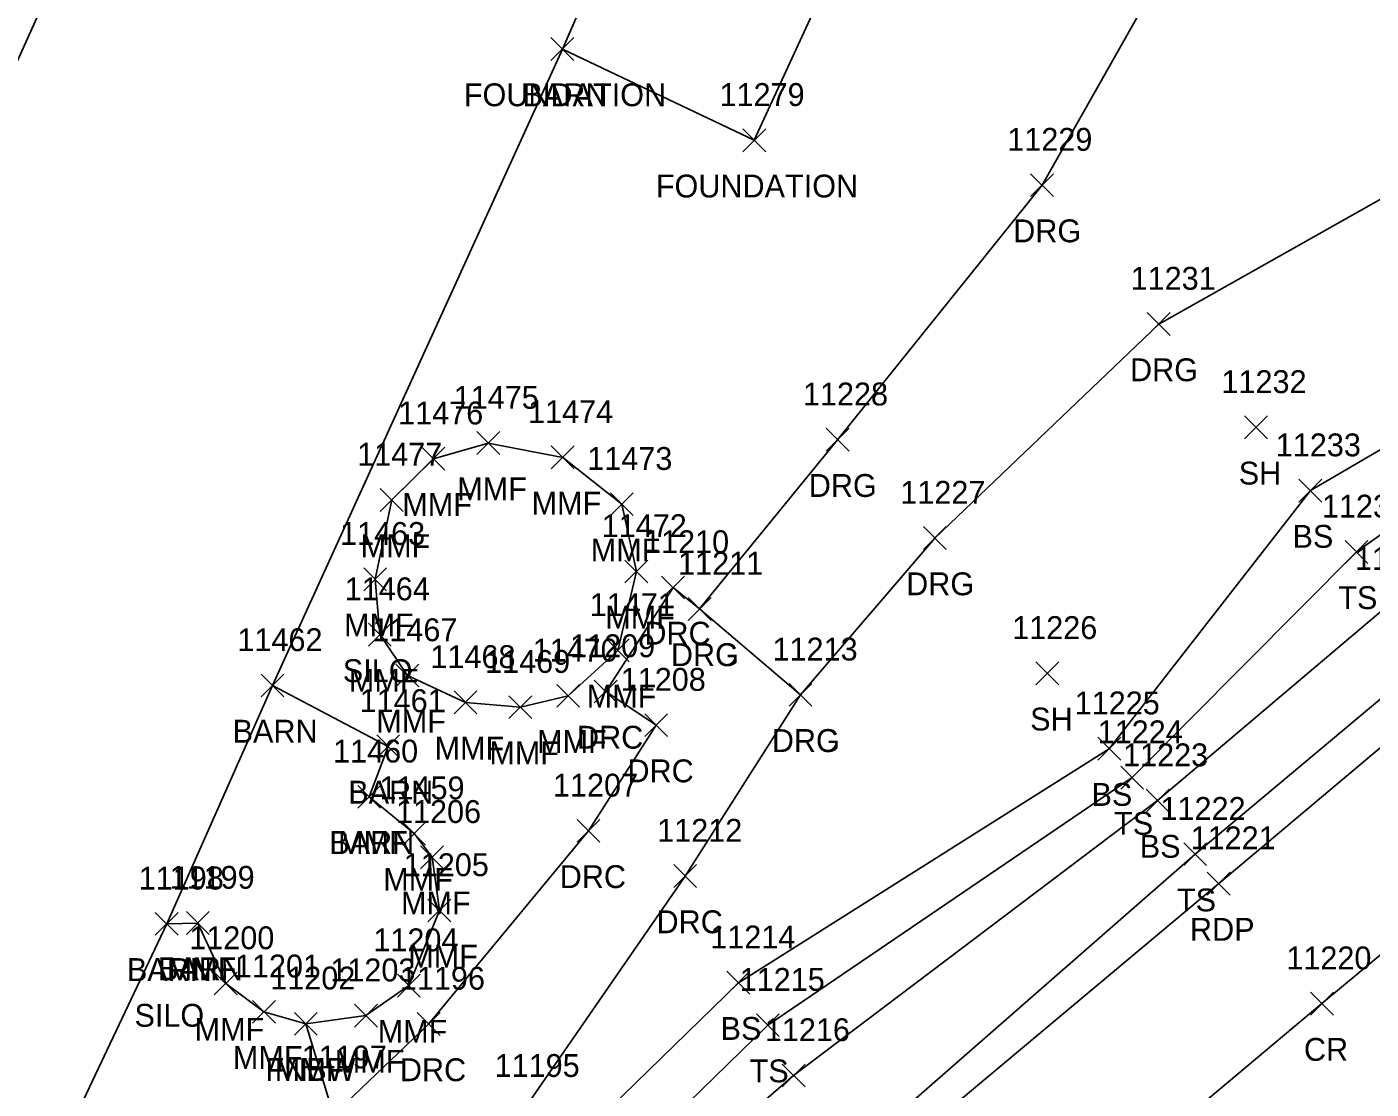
# Model space of a CAD drawing. Extents: x 1475671 to 1477951, y 592661 to 593821.
# Drawn here: x 1476740.9 to 1476858.4, y 593332 to 593424.9 of the extents above; entities that cross this region are included whole.
import ezdxf

# ---------------------------------------------------------------- set-up
doc = ezdxf.new("R2010")
doc.units = 0
for name, color, linetype in [('L_A', 7, 'Continuous'), ('L_C', 7, 'Continuous'), ('L_I', 7, 'Continuous'), ('L_TIC', 7, 'Continuous'), ('LBC', 7, 'Continuous'), ('LDEFAULT', 7, 'Continuous'), ('LELB', 7, 'Continuous'), ('LFNC', 7, 'Continuous'), ('P_A', 7, 'Continuous'), ('P_I', 7, 'Continuous'), ('P_TIC', 7, 'Continuous'), ('PET', 7, 'Continuous'), ('PRC', 7, 'Continuous'), ('R_A', 7, 'Continuous'), ('R_I', 7, 'Continuous'), ('R_TIC', 7, 'Continuous'), ('RDG', 7, 'Continuous'), ('RDP', 7, 'Continuous')]:
    doc.layers.add(name, color=color, linetype=linetype)

msp = doc.modelspace()

# ---------------------------------------------------------------- linework, layer by layer
at = {"layer": 'L_TIC'}
for points in [[(1476786.68, 593422.01), (1476788.68, 593424.01)], [(1476788.68, 593422.01), (1476786.68, 593424.01)], [(1476786.68, 593422.01), (1476788.68, 593424.01)], [(1476788.68, 593422.01), (1476786.68, 593424.01)], [(1476803.46, 593414.03), (1476805.46, 593416.03)], [(1476805.46, 593414.03), (1476803.46, 593416.03)], [(1476847.31, 593388.92), (1476849.31, 593390.92)], [(1476849.31, 593388.92), (1476847.31, 593390.92)], [(1476780.21, 593387.55), (1476782.21, 593389.55)], [(1476782.21, 593387.55), (1476780.21, 593389.55)], [(1476775.41, 593386.18), (1476777.41, 593388.18)], [(1476777.41, 593386.18), (1476775.41, 593388.18)], [(1476786.71, 593386.3), (1476788.71, 593388.3)], [(1476788.71, 593386.3), (1476786.71, 593388.3)], [(1476771.77, 593382.57), (1476773.77, 593384.57)], [(1476773.77, 593382.57), (1476771.77, 593384.57)], [(1476771.77, 593382.57), (1476773.77, 593384.57)], [(1476773.77, 593382.57), (1476771.77, 593384.57)], [(1476852.06, 593383.39), (1476854.06, 593385.39)], [(1476854.06, 593383.39), (1476852.06, 593385.39)], [(1476791.88, 593382.2), (1476793.88, 593384.2)], [(1476793.88, 593382.2), (1476791.88, 593384.2)], [(1476856.09, 593378.03), (1476858.09, 593380.03)], [(1476858.09, 593378.03), (1476856.09, 593380.03)], [(1476770.32, 593375.64), (1476772.32, 593377.64)], [(1476772.32, 593375.64), (1476770.32, 593377.64)], [(1476770.32, 593375.64), (1476772.32, 593377.64)], [(1476772.32, 593375.64), (1476770.32, 593377.64)], [(1476793.15, 593376.32), (1476795.15, 593378.32)], [(1476795.15, 593376.32), (1476793.15, 593378.32)], [(1476770.73, 593370.8), (1476772.73, 593372.8)], [(1476772.73, 593370.8), (1476770.73, 593372.8)], [(1476791.53, 593369.42), (1476793.53, 593371.42)], [(1476793.53, 593369.42), (1476791.53, 593371.42)], [(1476829.08, 593367.41), (1476831.08, 593369.41)], [(1476831.08, 593367.41), (1476829.08, 593369.41)], [(1476761.35, 593366.35), (1476763.35, 593368.35)], [(1476763.35, 593366.35), (1476761.35, 593368.35)], [(1476761.35, 593366.35), (1476763.35, 593368.35)], [(1476763.35, 593366.35), (1476761.35, 593368.35)], [(1476773.14, 593367.22), (1476775.14, 593369.22)], [(1476775.14, 593367.22), (1476773.14, 593369.22)], [(1476787.19, 593365.44), (1476789.19, 593367.44)], [(1476789.19, 593365.44), (1476787.19, 593367.44)], [(1476778.22, 593364.87), (1476780.22, 593366.87)], [(1476780.22, 593364.87), (1476778.22, 593366.87)], [(1476783.01, 593364.45), (1476785.01, 593366.45)], [(1476785.01, 593364.45), (1476783.01, 593366.45)], [(1476771.46, 593361.02), (1476773.46, 593363.02)], [(1476773.46, 593361.02), (1476771.46, 593363.02)], [(1476834.49, 593360.82), (1476836.49, 593362.82)], [(1476836.49, 593360.82), (1476834.49, 593362.82)], [(1476836.49, 593358.29), (1476838.49, 593360.29)], [(1476838.49, 593358.29), (1476836.49, 593360.29)], [(1476769.8, 593356.61), (1476771.8, 593358.61)], [(1476771.8, 593356.61), (1476769.8, 593358.61)], [(1476769.8, 593356.61), (1476771.8, 593358.61)], [(1476771.8, 593356.61), (1476769.8, 593358.61)], [(1476838.71, 593356.28), (1476840.71, 593358.28)], [(1476840.71, 593356.28), (1476838.71, 593358.28)], [(1476773.73, 593353.39), (1476775.73, 593355.39)], [(1476775.73, 593353.39), (1476773.73, 593355.39)], [(1476775.29, 593351.32), (1476777.29, 593353.32)], [(1476777.29, 593351.32), (1476775.29, 593353.32)], [(1476841.99, 593351.59), (1476843.99, 593353.59)], [(1476843.99, 593351.59), (1476841.99, 593353.59)], [(1476775.93, 593346.67), (1476777.93, 593348.67)], [(1476777.93, 593346.67), (1476775.93, 593348.67)], [(1476752.1, 593345.5), (1476754.1, 593347.5)], [(1476754.1, 593345.5), (1476752.1, 593347.5)], [(1476752.1, 593345.5), (1476754.1, 593347.5)], [(1476754.1, 593345.5), (1476752.1, 593347.5)], [(1476754.82, 593345.57), (1476756.82, 593347.57)], [(1476756.82, 593345.57), (1476754.82, 593347.57)], [(1476754.82, 593345.57), (1476756.82, 593347.57)], [(1476756.82, 593345.57), (1476754.82, 593347.57)], [(1476757.26, 593340.28), (1476759.26, 593342.28)], [(1476759.26, 593340.28), (1476757.26, 593342.28)], [(1476802.07, 593340.35), (1476804.07, 593342.35)], [(1476804.07, 593340.35), (1476802.07, 593342.35)], [(1476773.26, 593340.1), (1476775.26, 593342.1)], [(1476775.26, 593340.1), (1476773.26, 593342.1)], [(1476760.6, 593337.81), (1476762.6, 593339.81)], [(1476762.6, 593337.81), (1476760.6, 593339.81)], [(1476764.26, 593336.76), (1476766.26, 593338.76)], [(1476766.26, 593336.76), (1476764.26, 593338.76)], [(1476764.26, 593336.76), (1476766.26, 593338.76)], [(1476766.26, 593336.76), (1476764.26, 593338.76)], [(1476769.51, 593337.47), (1476771.51, 593339.47)], [(1476771.51, 593337.47), (1476769.51, 593339.47)], [(1476804.64, 593336.64), (1476806.64, 593338.64)], [(1476806.64, 593336.64), (1476804.64, 593338.64)], [(1476806.89, 593332.24), (1476808.89, 593334.24)], [(1476808.89, 593332.24), (1476806.89, 593334.24)]]:
    msp.add_lwpolyline(points, dxfattribs=at)
at = {"layer": 'LBC'}
for points in [[(1476766.99, 593478.72), (1476749.47, 593442.92), (1476737.05, 593415.38), (1476717.88, 593373.12), (1476703.46, 593340.35), (1476741.92, 593322.87), (1476753.1, 593346.5), (1476762.35, 593367.35), (1476787.68, 593423.01), (1476791.87, 593432.58)], [(1476803.32, 593462.28), (1476822.31, 593453.8), (1476804.46, 593415.03), (1476787.68, 593423.01)], [(1476770.8, 593357.61), (1476772.46, 593362.02), (1476762.35, 593367.35)], [(1476753.1, 593346.5), (1476755.82, 593346.57)]]:
    msp.add_lwpolyline(points, dxfattribs=at)
at = {"layer": 'LDEFAULT'}
for points in [[(1476771.32, 593376.64), (1476771.73, 593371.8), (1476774.14, 593368.22), (1476779.22, 593365.87), (1476784.01, 593365.45), (1476788.19, 593366.44), (1476792.53, 593370.42), (1476794.15, 593377.32), (1476792.88, 593383.2), (1476787.71, 593387.3), (1476781.21, 593388.55), (1476776.41, 593387.18), (1476772.77, 593383.57)], [(1476771.32, 593376.64), (1476772.77, 593383.57)], [(1476755.82, 593346.57), (1476758.26, 593341.28), (1476761.6, 593338.81), (1476765.26, 593337.76), (1476770.51, 593338.47), (1476774.26, 593341.1), (1476776.93, 593347.67), (1476776.29, 593352.32), (1476774.73, 593354.39), (1476770.8, 593357.61)]]:
    msp.add_lwpolyline(points, dxfattribs=at)
at = {"layer": 'LELB'}
for points in [[(1476660.79, 593199.46), (1476674.63, 593214.33), (1476703.92, 593243.37), (1476720.54, 593255.98), (1476751.7, 593282.61), (1476781.77, 593307.79), (1476789.04, 593316.89), (1476807.89, 593333.24), (1476839.71, 593357.28), (1476859.97, 593374.46), (1476882.16, 593391.96), (1476882.87, 593395.08), (1476884.75, 593398.78), (1476886.94, 593401.06), (1476880.92, 593405.09), (1476872.21, 593402.61), (1476869.35, 593406.91), (1476883.46, 593416.6), (1476894.87, 593423.54), (1476922.16, 593439.01), (1476941.74, 593451.3), (1476958.3, 593465.19), (1476973.77, 593478.9)], [(1476525.71, 593116.6), (1476535.99, 593117.47), (1476564.39, 593135.96), (1476604.97, 593161.16), (1476624.83, 593173.86), (1476638.09, 593183.34), (1476660.79, 593199.46), (1476676.81, 593212.32), (1476707.13, 593238.69), (1476723.81, 593252.6), (1476754.14, 593278.44), (1476785.31, 593303.01), (1476812.8, 593326.19), (1476842.99, 593352.59), (1476863.07, 593369.43), (1476886.56, 593389.77), (1476893.66, 593396.85), (1476901.2, 593401.68), (1476921.17, 593422.2)], [(1476709.5, 593251.9), (1476704.63, 593270.28), (1476699.34, 593285.3), (1476723.21, 593287.69), (1476755.77, 593298.72), (1476777.04, 593314.27), (1476785.1, 593323.82), (1476803.07, 593341.35), (1476835.49, 593361.82), (1476853.06, 593384.39), (1476874.85, 593397.11), (1476884.75, 593398.78)], [(1476716.55, 593257.09), (1476712.45, 593265.92), (1476725.15, 593279.89), (1476757.78, 593295.95), (1476779.66, 593309.61), (1476787.04, 593319.52), (1476805.64, 593337.64), (1476837.49, 593359.29), (1476857.09, 593379.03), (1476877.34, 593393.41), (1476882.87, 593395.08)]]:
    msp.add_lwpolyline(points, dxfattribs=at)
at = {"layer": 'LFNC'}
msp.add_lwpolyline([(1476767.35, 593330.85), (1476765.26, 593337.76)], dxfattribs=at)
at = {"layer": 'P_TIC'}
for points in [[(1476844.05, 593349.02), (1476846.05, 593351.02)], [(1476846.05, 593349.02), (1476844.05, 593351.02)], [(1476853.07, 593338.52), (1476855.07, 593340.52)], [(1476855.07, 593338.52), (1476853.07, 593340.52)]]:
    msp.add_lwpolyline(points, dxfattribs=at)
at = {"layer": 'PET'}
msp.add_lwpolyline([(1476459.25, 593078.48), (1476508.39, 593100.17), (1476518.15, 593105.13), (1476565.38, 593131.07), (1476607.43, 593157.45), (1476640.25, 593180.54), (1476678.21, 593210.57), (1476708.64, 593235.75), (1476725.67, 593249.83), (1476755.84, 593275.3), (1476786.3, 593300.73), (1476814.32, 593324.28), (1476845.05, 593350.02), (1476865.02, 593366.82), (1476897.04, 593395.14), (1476922.98, 593419.08), (1476952.36, 593443.37)], dxfattribs=at)
at = {"layer": 'PRC'}
msp.add_lwpolyline([(1476461.98, 593064.62), (1476520.7, 593090.52), (1476540.79, 593101.34), (1476577.67, 593121.61), (1476614.51, 593145.69), (1476649.36, 593170.81), (1476687.02, 593200.01), (1476716.69, 593224.25), (1476733.58, 593238.31), (1476760.9, 593261.21), (1476795.35, 593290.14), (1476823.06, 593313.51), (1476854.07, 593339.52), (1476875.7, 593357.51), (1476907.01, 593384.08), (1476934.06, 593407.68), (1476963.46, 593432.81)], dxfattribs=at)
at = {"layer": 'R_TIC'}
for points in [[(1476828.61, 593410.11), (1476830.61, 593412.11)], [(1476830.61, 593410.11), (1476828.61, 593412.11)], [(1476838.81, 593397.96), (1476840.81, 593399.96)], [(1476840.81, 593397.96), (1476838.81, 593399.96)], [(1476810.74, 593387.84), (1476812.74, 593389.84)], [(1476812.74, 593387.84), (1476810.74, 593389.84)], [(1476819.24, 593379.24), (1476821.24, 593381.24)], [(1476821.24, 593379.24), (1476819.24, 593381.24)], [(1476796.36, 593374.92), (1476798.36, 593376.92)], [(1476798.36, 593374.92), (1476796.36, 593376.92)], [(1476798.68, 593373.04), (1476800.68, 593375.04)], [(1476800.68, 593373.04), (1476798.68, 593375.04)], [(1476798.68, 593373.04), (1476800.68, 593375.04)], [(1476800.68, 593373.04), (1476798.68, 593375.04)], [(1476790.47, 593365.82), (1476792.47, 593367.82)], [(1476792.47, 593365.82), (1476790.47, 593367.82)], [(1476807.5, 593365.53), (1476809.5, 593367.53)], [(1476809.5, 593365.53), (1476807.5, 593367.53)], [(1476807.5, 593365.53), (1476809.5, 593367.53)], [(1476809.5, 593365.53), (1476807.5, 593367.53)], [(1476807.5, 593365.53), (1476809.5, 593367.53)], [(1476809.5, 593365.53), (1476807.5, 593367.53)], [(1476794.88, 593362.88), (1476796.88, 593364.88)], [(1476796.88, 593362.88), (1476794.88, 593364.88)], [(1476788.97, 593353.63), (1476790.97, 593355.63)], [(1476790.97, 593353.63), (1476788.97, 593355.63)], [(1476797.42, 593349.68), (1476799.42, 593351.68)], [(1476799.42, 593349.68), (1476797.42, 593351.68)], [(1476774.99, 593336.74), (1476776.99, 593338.74)], [(1476776.99, 593336.74), (1476774.99, 593338.74)]]:
    msp.add_lwpolyline(points, dxfattribs=at)
at = {"layer": 'RDG'}
for points in [[(1476799.68, 593374.04), (1476811.74, 593388.84), (1476829.61, 593411.11), (1476841.26, 593431.75), (1476824.79, 593454.41)], [(1476808.5, 593366.53), (1476820.24, 593380.24), (1476839.81, 593398.96), (1476864.37, 593412.81), (1476894.87, 593423.54), (1476911.77, 593427.3), (1476921.17, 593422.2), (1476922.98, 593419.08)]]:
    msp.add_lwpolyline(points, dxfattribs=at)
at = {"layer": 'RDP'}
for points in [[(1476741.92, 593322.87), (1476748.15, 593317.64), (1476764.24, 593326.49), (1476775.99, 593337.74), (1476789.97, 593354.63), (1476795.88, 593363.88), (1476791.47, 593366.82), (1476797.36, 593375.92), (1476799.68, 593374.04), (1476808.5, 593366.53)], [(1476703.46, 593340.35), (1476696.1, 593322.41), (1476695.07, 593307.68), (1476704.77, 593300.24), (1476724.04, 593301.34), (1476733.81, 593300.45), (1476747.14, 593305.07), (1476767.96, 593315.71), (1476784.22, 593330.11), (1476798.42, 593350.68), (1476808.5, 593366.53)]]:
    msp.add_lwpolyline(points, dxfattribs=at)

# ---------------------------------------------------------------- texts
at = {"layer": 'L_A'}
for s, p in [('FOUNDATION', (1476779.07, 593418.01)), ('BARN', (1476784.19, 593418.01)), ('FOUNDATION', (1476795.85, 593410.03)), ('SH', (1476846.8, 593384.92)), ('MMF', (1476778.49, 593383.55)), ('MMF', (1476773.69, 593382.18)), ('MMF', (1476784.99, 593382.3)), ('BS', (1476851.5, 593379.39)), ('MMF', (1476770.05, 593378.57)), ('MMF', (1476770.05, 593378.57)), ('MMF', (1476790.16, 593378.2)), ('TS', (1476855.5, 593374.03)), ('MMF', (1476791.43, 593372.32)), ('MMF', (1476768.6, 593371.64)), ('MMF', (1476768.6, 593371.64)), ('MMF', (1476769.02, 593366.8)), ('MMF', (1476789.81, 593365.42)), ('MMF', (1476771.42, 593363.22)), ('SH', (1476828.57, 593363.41)), ('BARN', (1476758.86, 593362.35)), ('BARN', (1476758.86, 593362.35)), ('MMF', (1476785.47, 593361.44)), ('MMF', (1476776.51, 593360.87)), ('MMF', (1476781.3, 593360.45)), ('BARN', (1476768.97, 593357.02)), ('BS', (1476833.93, 593356.82)), ('TS', (1476835.9, 593354.29)), ('BARN', (1476767.31, 593352.61)), ('MMF', (1476768.08, 593352.61)), ('BS', (1476838.15, 593352.28)), ('MMF', (1476772.02, 593349.39)), ('MMF', (1476773.58, 593347.32)), ('TS', (1476841.4, 593347.59)), ('MMF', (1476774.21, 593342.67)), ('BARN', (1476749.62, 593341.5)), ('BARN', (1476749.62, 593341.5)), ('BARN', (1476752.33, 593341.57)), ('MMF', (1476753.1, 593341.57)), ('MMF', (1476755.54, 593336.28)), ('MMF', (1476771.54, 593336.1)), ('BS', (1476801.51, 593336.35)), ('MMF', (1476758.88, 593333.81)), ('MMF', (1476767.79, 593333.47)), ('FNBW', (1476761.73, 593332.76)), ('MMF', (1476762.54, 593332.76)), ('TS', (1476804.05, 593332.64))]:
    msp.add_text(s, height=2, dxfattribs=at).set_placement(p)
at = {"layer": 'L_C'}
for p in [(1476768.49, 593367.64), (1476768.49, 593367.64), (1476750.28, 593337.5), (1476750.28, 593337.5)]:
    msp.add_text('SILO', height=2, dxfattribs=at).set_placement(p)
at = {"layer": 'L_I'}
for s, p in [('11279', (1476801.42, 593418.03)), ('11232', (1476845.29, 593392.92)), ('11475', (1476778.18, 593391.55)), ('11476', (1476773.33, 593390.18)), ('11474', (1476784.68, 593390.3)), ('11233', (1476850.04, 593387.39)), ('11477', (1476769.75, 593386.57)), ('11477', (1476769.75, 593386.57)), ('11473', (1476789.86, 593386.2)), ('11234', (1476854.07, 593382.03)), ('11472', (1476791.12, 593380.32)), ('11463', (1476768.25, 593379.64)), ('11463', (1476768.25, 593379.64)), ('11235', (1476856.95, 593377.46)), ('11464', (1476768.66, 593374.8)), ('11471', (1476790.07, 593373.42)), ('11467', (1476771.07, 593371.22)), ('11226', (1476827, 593371.41)), ('11462', (1476759.28, 593370.35)), ('11462', (1476759.28, 593370.35)), ('11468', (1476776.15, 593368.87)), ('11469', (1476780.93, 593368.45)), ('11470', (1476785.08, 593369.44)), ('11461', (1476769.96, 593365.02)), ('11225', (1476832.46, 593364.82)), ('11224', (1476834.47, 593362.29)), ('11460', (1476767.64, 593360.61)), ('11460', (1476767.64, 593360.61)), ('11223', (1476836.69, 593360.28)), ('11459', (1476771.7, 593357.39)), ('11222', (1476839.96, 593355.59)), ('11206', (1476773.14, 593355.32)), ('11205', (1476773.82, 593350.67)), ('11198', (1476750.65, 593349.5)), ('11198', (1476750.65, 593349.5)), ('11199', (1476753.35, 593349.57)), ('11199', (1476753.35, 593349.57)), ('11200', (1476755.07, 593344.28)), ('11204', (1476771.16, 593344.1)), ('11214', (1476800.61, 593344.35)), ('11201', (1476759.06, 593341.81)), ('11203', (1476767.4, 593341.47)), ('11202', (1476762.15, 593340.76)), ('11202', (1476762.15, 593340.76)), ('11215', (1476803.18, 593340.64)), ('11216', (1476805.38, 593336.24)), ('11197', (1476764.9, 593333.85))]:
    msp.add_text(s, height=2, dxfattribs=at).set_placement(p)
at = {"layer": 'P_A'}
for s, p in [('RDP', (1476842.54, 593345.02)), ('CR', (1476852.5, 593334.52))]:
    msp.add_text(s, height=2, dxfattribs=at).set_placement(p)
at = {"layer": 'P_I'}
for s, p in [('11221', (1476842.59, 593353.02)), ('11220', (1476850.96, 593342.52))]:
    msp.add_text(s, height=2, dxfattribs=at).set_placement(p)
at = {"layer": 'R_A'}
for s, p in [('DRG', (1476827.09, 593406.11)), ('DRG', (1476837.3, 593393.96)), ('DRG', (1476809.22, 593383.84)), ('DRG', (1476817.73, 593375.24)), ('DRC', (1476794.85, 593370.92)), ('DRC', (1476797.17, 593369.04)), ('DRG', (1476797.17, 593369.04)), ('DRC', (1476788.96, 593361.82)), ('DRC', (1476805.99, 593361.53)), ('DRC', (1476805.99, 593361.53)), ('DRG', (1476805.99, 593361.53)), ('DRC', (1476793.37, 593358.88)), ('DRC', (1476787.45, 593349.63)), ('DRC', (1476795.91, 593345.68)), ('DRC', (1476773.48, 593332.74))]:
    msp.add_text(s, height=2, dxfattribs=at).set_placement(p)
at = {"layer": 'R_I'}
for s, p in [('11229', (1476826.57, 593414.11)), ('11231', (1476837.35, 593401.96)), ('11228', (1476808.71, 593391.84)), ('11227', (1476817.22, 593383.24)), ('11210', (1476794.82, 593378.92)), ('11211', (1476797.8, 593377.04)), ('11211', (1476797.8, 593377.04)), ('11209', (1476788.36, 593369.82)), ('11213', (1476806.05, 593369.53)), ('11213', (1476806.05, 593369.53)), ('11213', (1476806.05, 593369.53)), ('11208', (1476792.78, 593366.88)), ('11207', (1476786.86, 593357.63)), ('11212', (1476795.97, 593353.68)), ('11196', (1476773.48, 593340.74)), ('11195', (1476781.76, 593333.11))]:
    msp.add_text(s, height=2, dxfattribs=at).set_placement(p)

doc.saveas('drawing.dxf')
